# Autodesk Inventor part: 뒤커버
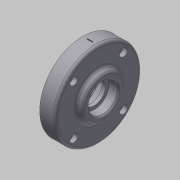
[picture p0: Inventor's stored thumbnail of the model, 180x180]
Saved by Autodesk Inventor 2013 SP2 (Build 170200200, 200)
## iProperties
Company: 한국ATC센터
Created: 2015-12
Part Number: 뒤커버
Document SubType Name: Modeling
Designer: mdu
Density: 2.71 g/cm^3
Mass: 97.9591 g
Surface Area: 115.525 cm^2
Volume: 36.1473 cm^3
Material: 알루미늄-6061
Author: mdu
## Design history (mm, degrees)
sketch "스케치1"
  geometry: L1 (-10.5, 0)-(10.5, 0); L2 (10.5, 0)-(10.5, 22.5); L3 (10.5, 22.5)-(5.5, 22.5); L4 (5.5, 22.5)-(5.5, 32.5); L5 (5.5, 32.5)-(-6.5, 32.5); L6 (-6.5, 32.5)-(-6.5, 17.5); L7 (-6.5, 17.5)-(-10.5, 15.191); L8 (-10.5, 15.191)-(-10.5, 0); 2 further points
  constraints: 16 end point, 3 parallel, 3 perpendicular, 1 coincident, 1 horizontal, 1 midpoint
  dimensions: "d0" = 21 distance of L1.start L1.end; "d1" = 65 diameter of L5 L1; "d2" = 45 diameter of L3 L1; "d3" = 35 diameter of L6.end L1; "d4" = 120 deg angle of L7 L6; "d5" = 12 distance of L4.end L5.end; "d6" = 5 distance of L2.end L3.end
revolve "회전1" sketch "스케치1" stored, may be unused: angle "d7" = 90 deg
sketch "스케치2"
  geometry: L1 (0, 0)-(32.5, 0); L2 (0, 0)-(18.738, 18.738); 1 further point
  constraints: 4 end point, 1 horizontal, 1 horizontal alignment, 1 other
  dimensions: "d8" = 45 deg angle of L1 L2; "d9" = 26.5 distance of L1.start L2.end
hole "구멍1" sketch "스케치2" at (18.738, 18.738) diameter "d10" = 3.4; stored, may be unused: countersink angle "d14" = 90 deg, drill point angle "d16" = 118 deg; dims "d11" = 6, "d12" = 6, "d13" = 3.3, "d15" = 8
fillet "모깎기1" dims "d20" = 2
hole "구멍2" diameter "d23" = 15; stored, may be unused: countersink angle "d27" = 90 deg, drill point angle "d29" = 0 deg; dims "d21" = 10, "d22" = 10, "d24" = 6, "d25" = 35, "d26" = 11, "d28" = 14
chamfer "모따기1" distance "d39" = 1; stored, may be unused: second distance "d40" = 2, angle "d41" = 45 deg
fillet "모깎기2" dims "d42" = 0.3
hole "구멍4" diameter "d46" = 17; stored, may be unused: countersink angle "d50" = 90 deg, drill point angle "d52" = 118 deg; dims "d44" = 10, "d45" = 10, "d47" = 6, "d48" = 22, "d49" = 7.3, "d51" = 8
chamfer "모따기2" distance "d53" = 1; stored, may be unused: second distance "d54" = 2, angle "d55" = 45 deg
fillet "모깎기3" dims "d56" = 0.3
node "작업 평면1"
sketch "스케치3"
  geometry: 2 further points
  constraints: 1 coincident, 1 other
feature "엠보싱1" sketch "스케치3" dims "d0" = 21, "d1" = 65, "d2" = 45, "d3" = 35, "d4" = 120 deg, "d5" = 12, "d6" = 5, "d58" = 0.3, "d59" = 0
fillet "모깎기4" dims "d60" = 0.2
fillet "모깎기5" dims "d61" = 0.1
node "솔리드1"
pattern_circular "원형 패턴1" dims angle "d18" = 360 deg
